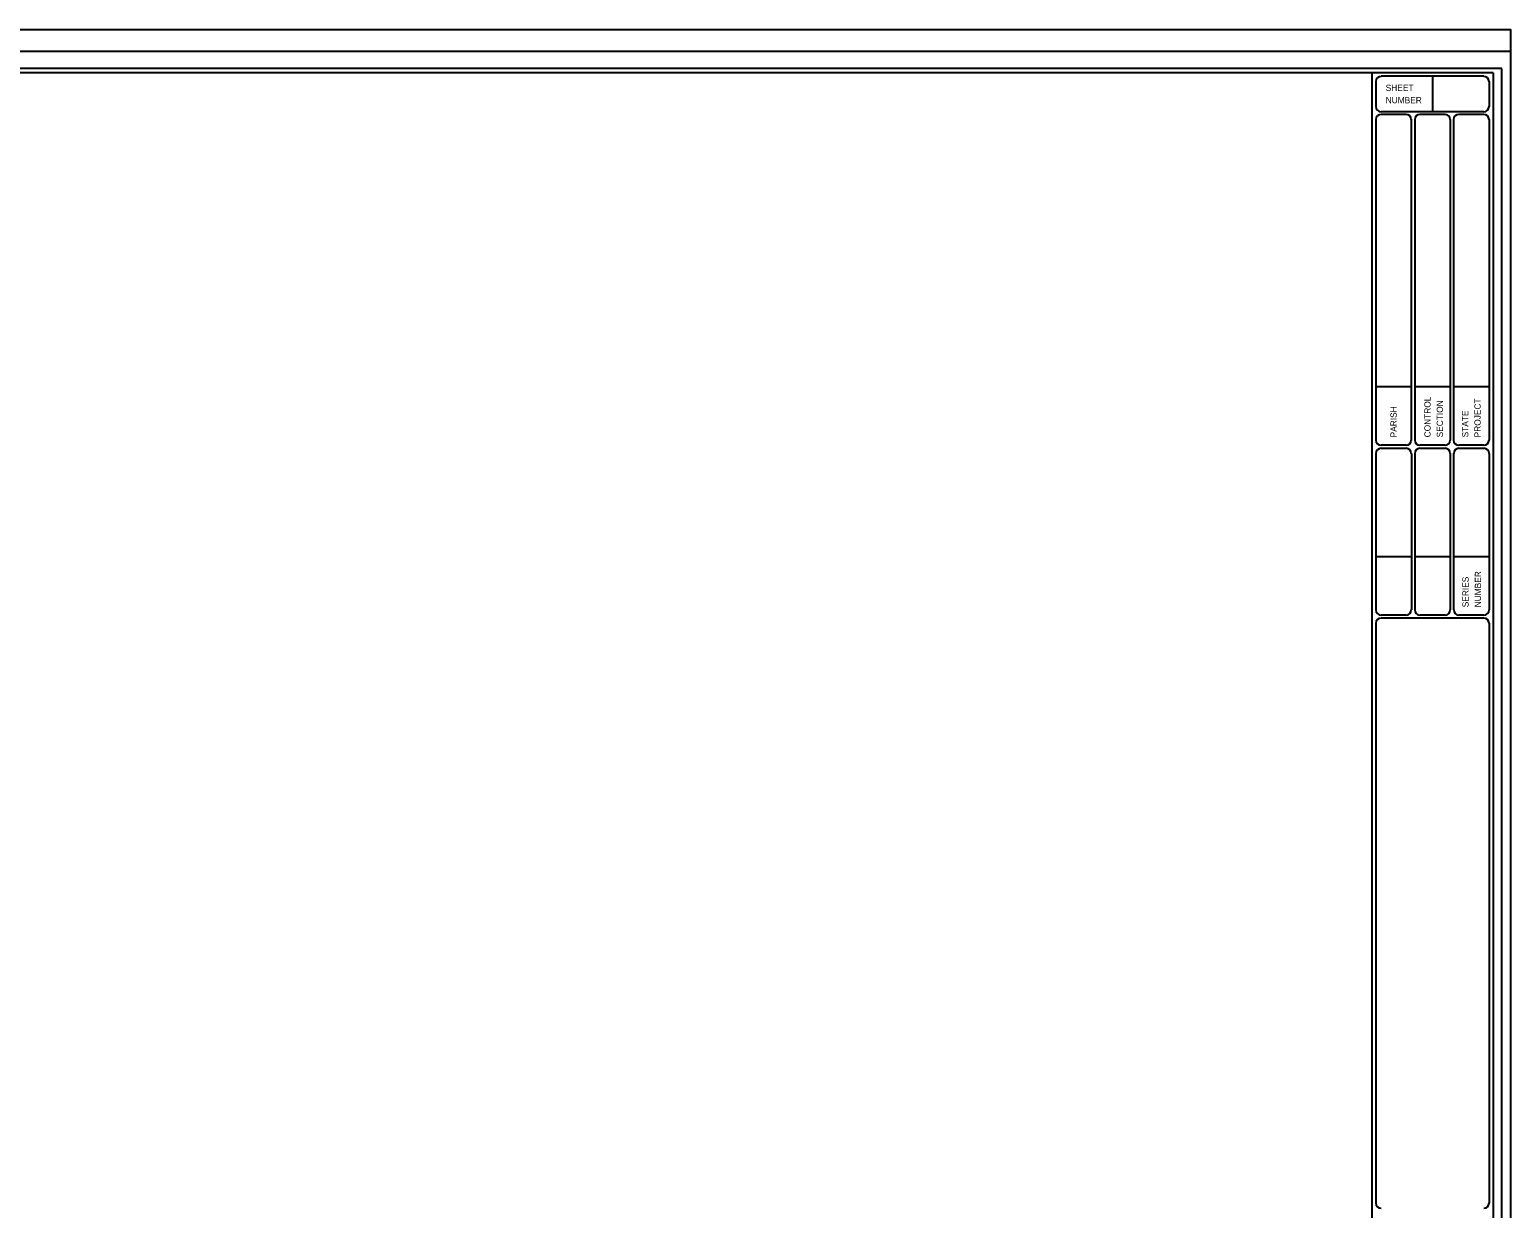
# Model space of a CAD drawing. Extents: x -0.02 to 2.83, y -0.02 to 1.85.
# Drawn here: x 1.408 to 2.833, y 0.698 to 1.833 of the extents above; entities that cross this region are included whole.
import ezdxf

# ---------------------------------------------------------------- set-up
doc = ezdxf.new("R2010")
doc.units = 0
for name, color, linetype in [('Plot Border', 7, 'Continuous'), ('Plot Border 2', 7, 'Continuous'), ('Sheet Border', 7, 'Continuous')]:
    doc.layers.add(name, color=color, linetype=linetype)

msp = doc.modelspace()

# ---------------------------------------------------------------- linework, layer by layer
at = {"layer": 'Plot Border'}
for points in [[(0, 1.8333), (2.8333, 1.8333), (2.8333, 0), (0, 0)], [(2.825, 1.7958), (0.075, 1.7958), (0.075, 0.0375), (2.825, 0.0375)]]:
    msp.add_lwpolyline(points, close=True, dxfattribs=at)
at = {"layer": 'Plot Border 2'}
msp.add_lwpolyline([(0, 1.8125), (2.8333, 1.8125), (2.8333, 0.0208), (0, 0.0208)], close=True, dxfattribs=at)
at = {"layer": 'Sheet Border'}
for p, q in [((2.8167, 1.7917), (0.1917, 1.7917)), ((2.7, 1.7917), (2.7, 0.0417)), ((2.7039, 1.7834), (2.7039, 1.7592)), ((2.8079, 1.7884), (2.7088, 1.7884)), ((2.7583, 1.7884), (2.7583, 1.7543)), ((2.8128, 1.7834), (2.8128, 1.7592)), ((2.8167, 1.7917), (2.8167, 0.0417)), ((2.8079, 1.7543), (2.7088, 1.7543)), ((2.7039, 1.747), (2.7039, 1.4379)), ((2.733, 1.7516), (2.7088, 1.7516)), ((2.7379, 1.7471), (2.7379, 1.4378)), ((2.7412, 1.7467), (2.7412, 1.4382)), ((2.7704, 1.7516), (2.7462, 1.7516)), ((2.7754, 1.7467), (2.7754, 1.4382)), ((2.7787, 1.7467), (2.7787, 1.4382)), ((2.8079, 1.7516), (2.7836, 1.7516)), ((2.8128, 1.7467), (2.8128, 1.4382)), ((2.7379, 1.4894), (2.7039, 1.4894)), ((2.7754, 1.4894), (2.7412, 1.4894)), ((2.8128, 1.4894), (2.7787, 1.4894)), ((2.7039, 1.4257), (2.7039, 1.2746)), ((2.733, 1.4333), (2.7088, 1.4333)), ((2.733, 1.4302), (2.7088, 1.4302)), ((2.7704, 1.4333), (2.7462, 1.4333)), ((2.7705, 1.4302), (2.7462, 1.4302)), ((2.7787, 1.4257), (2.7787, 1.2746)), ((2.8079, 1.4333), (2.7836, 1.4333)), ((2.8079, 1.4302), (2.7837, 1.4302)), ((2.738, 1.4253), (2.738, 1.2746)), ((2.7413, 1.4253), (2.7413, 1.2746)), ((2.7754, 1.4253), (2.7754, 1.2746)), ((2.8129, 1.4253), (2.8129, 1.2746)), ((2.7379, 1.3258), (2.7039, 1.3258)), ((2.7754, 1.3258), (2.7412, 1.3258)), ((2.8128, 1.3258), (2.7787, 1.3258)), ((2.733, 1.2697), (2.7088, 1.2697)), ((2.7705, 1.2697), (2.7462, 1.2697)), ((2.8079, 1.2697), (2.7837, 1.2697)), ((2.7039, 1.2619), (2.7039, 0.7034)), ((2.8079, 1.2668), (2.7088, 1.2668)), ((2.8128, 1.2619), (2.8128, 0.7034))]:
    msp.add_line(p, q, dxfattribs=at)
for centre, start, end in [((2.7088, 1.7834), 90, 180), ((2.8078, 1.7834), 0, 90), ((2.7088, 1.7592), 180, 270), ((2.8078, 1.7592), 270, 0), ((2.7088, 1.7467), 90, 180), ((2.733, 1.7467), 0, 90), ((2.7462, 1.7467), 90, 180), ((2.7704, 1.7467), 0, 90), ((2.7836, 1.7467), 90, 180), ((2.8078, 1.7467), 0, 90), ((2.7088, 1.4382), 180, 270), ((2.7088, 1.4253), 90, 180), ((2.733, 1.4382), 270, 0), ((2.733, 1.4253), 0, 90), ((2.7462, 1.4382), 180, 270), ((2.7462, 1.4253), 90, 180), ((2.7704, 1.4382), 270, 0), ((2.7705, 1.4253), 0, 90), ((2.7836, 1.4382), 180, 270), ((2.7837, 1.4253), 90, 180), ((2.8078, 1.4382), 270, 0), ((2.8079, 1.4253), 0, 90), ((2.7088, 1.2746), 180, 270), ((2.733, 1.2746), 270, 0), ((2.7462, 1.2746), 180, 270), ((2.7705, 1.2746), 270, 0), ((2.7837, 1.2746), 180, 270), ((2.8079, 1.2746), 270, 0), ((2.7088, 1.2619), 90, 180), ((2.8078, 1.2619), 0, 90), ((2.7088, 0.7035), 180, 270), ((2.8078, 0.7035), 270, 0)]:
    msp.add_arc(centre, 0.00495, start, end, dxfattribs=at)

# ---------------------------------------------------------------- texts
for s, p in [('SHEET', (2.7133, 1.7743)), ('NUMBER', (2.7133, 1.7624))]:
    msp.add_text(s, height=0.006, dxfattribs=at).set_placement(p)
for s, p in [('PARISH', (2.7239, 1.4408)), ('CONTROL', (2.7565, 1.4408)), ('SECTION', (2.7684, 1.4408)), ('PROJECT', (2.8047, 1.4408)), ('STATE', (2.7928, 1.4408)), ('NUMBER', (2.8051, 1.2772)), ('SERIES', (2.7931, 1.2772))]:
    msp.add_text(s, height=0.006, rotation=90, dxfattribs=at).set_placement(p)

doc.saveas('drawing.dxf')
